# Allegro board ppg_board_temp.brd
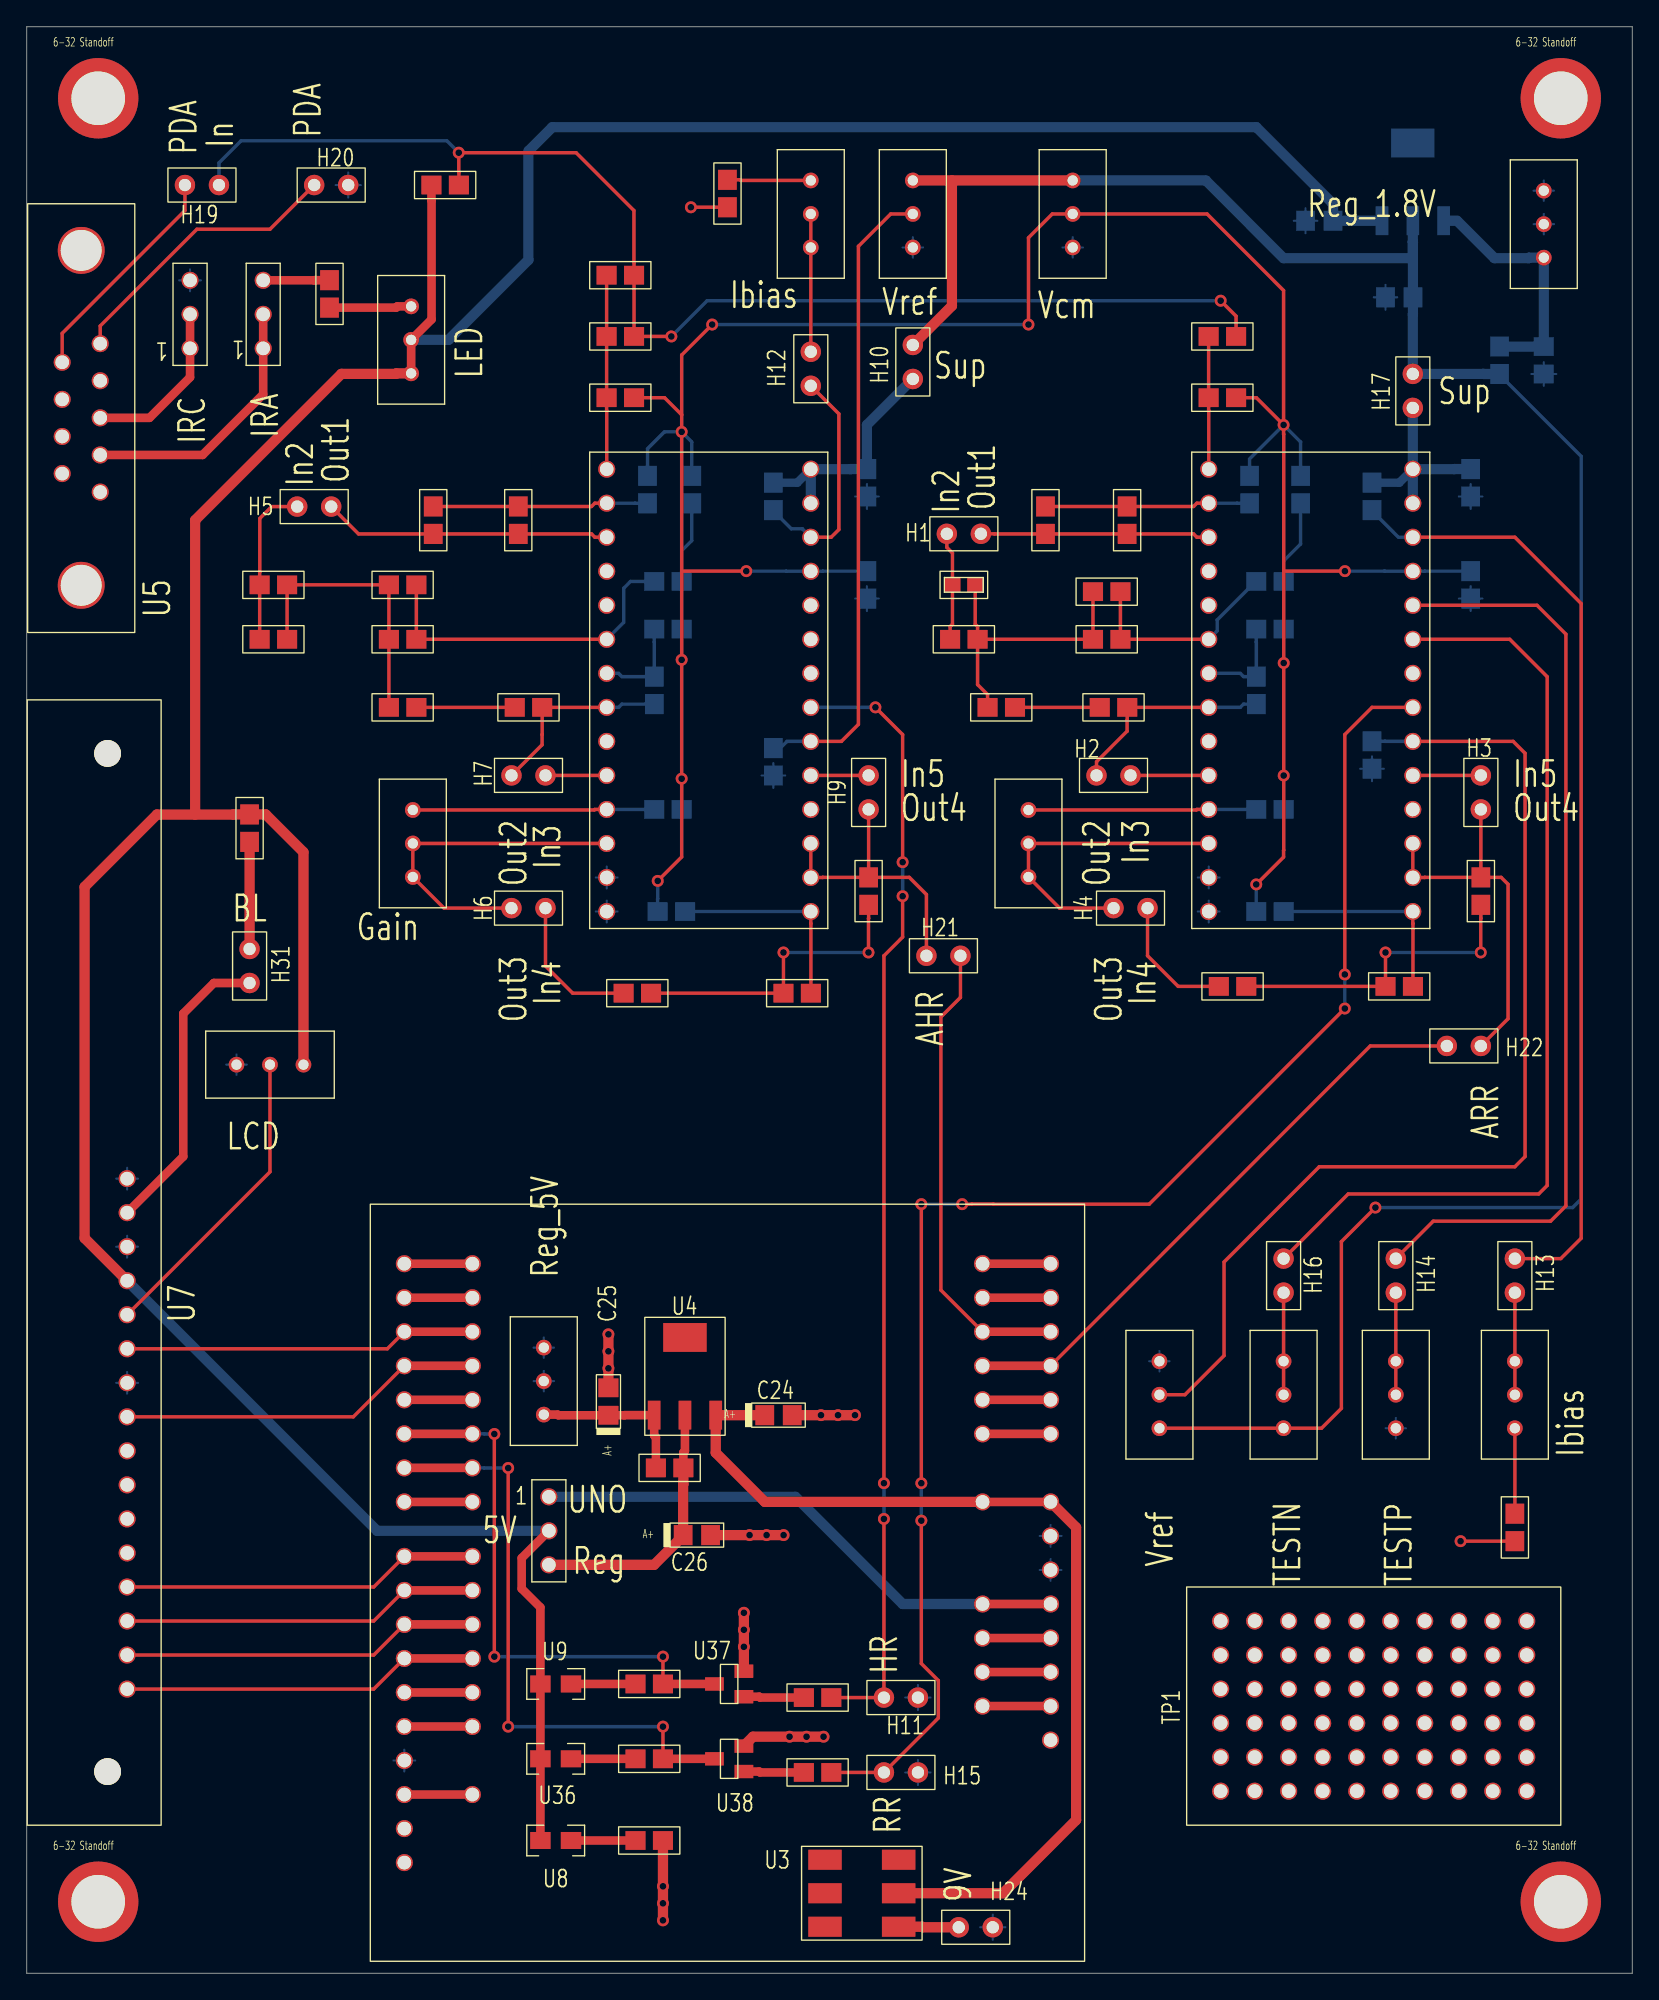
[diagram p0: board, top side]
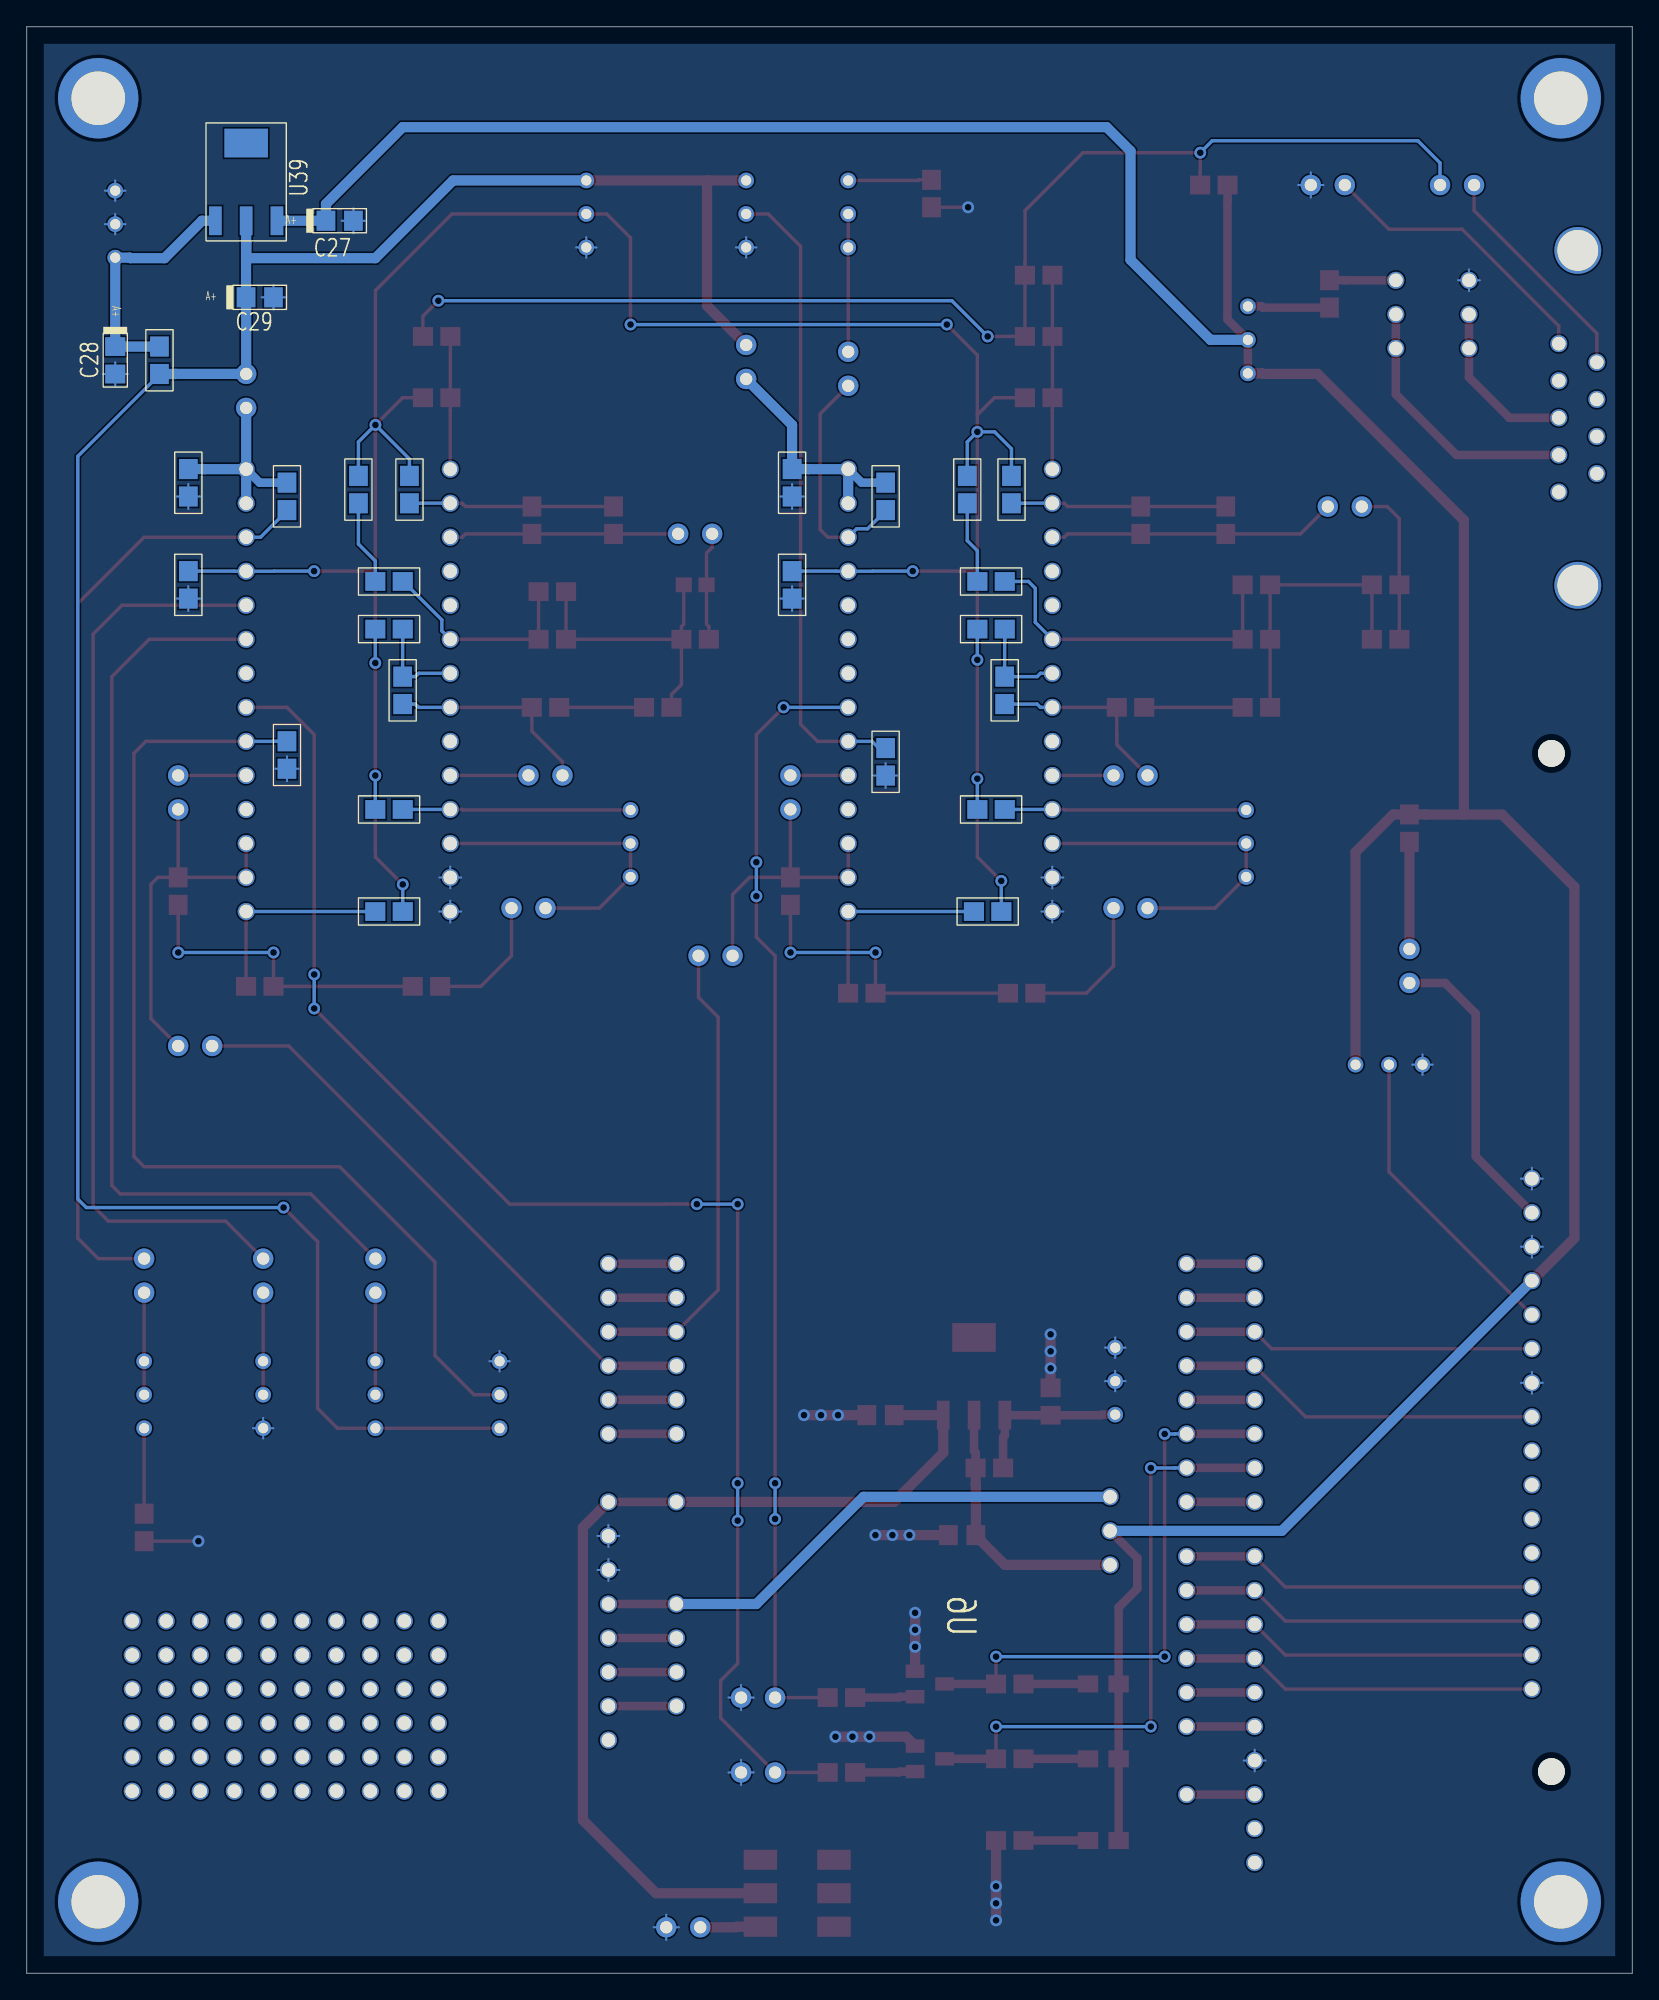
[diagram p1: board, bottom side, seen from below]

Outline 119.89 x 145.29 mm; copper layers: TOP, BOTTOM. Coordinates in mm from the lower left corner of the outline.
Outline path: 0,145.29 0,0 119.89,0 119.89,145.29 0,145.29

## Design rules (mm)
net group A: nets A<0> A<1> A<2> A<3> A<4> A<5>
net group PB: nets PB<0> PB<1> PB<2> PB<3> PB<4> PB<5>
net group PD: nets PD<0> PD<1> PD<2> PD<3> PD<4> PD<5> PD<6> PD<7>

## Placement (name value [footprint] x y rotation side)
C1  -  [GR_0805]  89.28 122.17 180 top
C2  -  [GR_0805]  82.17 108.46 270 top
C3  -  [GR_0603]  69.98 103.63 0 top
C4  -  [GR_0805]  69.98 99.57 0 top
C5  -  [GR_0805]  80.65 99.57 0 top
C6  -  [GR_0805]  80.65 103.12 0 top
C7  -  [GR_0805]  44.32 126.75 0 top
C8  -  [GR_0805]  44.32 122.17 0 top
C9  -  [GR_0805]  36.7 108.46 90 top
C10  -  [GR_0805]  18.41 103.63 180 top
C11  -  [GR_0805]  18.41 99.57 180 top
C12  -  [GR_0805]  28.07 99.57 180 top
C13  -  [GR_0805]  28.07 103.63 180 top
C14  -  [GR_0805]  48.13 79.25 0 bottom
C15  -  [GR_0805]  55.75 90.42 90 bottom
C16  -  [GR_0805]  62.74 103.63 90 bottom
C17  -  [GR_0805]  55.75 110.24 270 bottom
C18  -  [GR_0805]  100.46 110.24 270 bottom
C19  -  [GR_0805]  107.82 103.63 90 bottom
C20  -  [GR_0805]  62.87 80.77 90 top
C21  -  [GR_0805]  92.84 79.25 0 bottom
C22  -  [GR_0805]  108.59 80.77 270 top
C23  -  [GR_0805]  100.46 90.93 90 bottom
C24  -  [GR_0805_TANT]  56.13 41.66 0 top
C25  -  [GR_0805_TANT]  43.43 42.67 90 top
C26  -  [GR_0805_TANT]  50.04 32.7 0 top
C27  -  [GR_0805_TANT]  96.52 130.81 180 bottom
C28  -  [GR_0805_TANT]  113.28 120.4 270 bottom
C29  -  [GR_0805_TANT]  102.49 125.09 180 bottom
C30  -  [GR_0805]  62.74 111.25 90 bottom
C31  -  [GR_0805]  107.82 111.25 90 bottom
H1  -  [JUMPER2]  71.25 107.44 180 top
H2  -  [JUMPER2]  79.88 89.41 0 top
H3  -  [JUMPER2]  108.59 89.41 270 top
H4  -  [JUMPER2]  81.15 79.5 0 top
H5  -  [JUMPER2]  20.19 109.47 0 top
H6  -  [JUMPER2]  38.73 79.5 180 top
H7  -  [JUMPER2]  38.73 89.41 180 top
H8  -  [GR_HEADER_SIP3]  12.19 123.83 180 top
H9  -  [JUMPER2]  62.87 86.87 90 top
H10  -  [JUMPER2]  66.17 119 90 top
H11  -  [JUMPER2]  64.01 20.57 0 top
H12  -  [JUMPER2]  58.55 118.49 90 top
H13  -  [JUMPER2]  111.12 53.34 270 top
H14  -  [JUMPER2]  102.23 53.34 270 top
H15  -  [JUMPER2]  64.01 14.99 0 top
H16  -  [JUMPER2]  93.85 53.34 270 top
H17  -  [JUMPER2]  103.5 119.38 270 top
H18  -  [GR_HEADER_SIP3]  17.65 123.83 180 top
H19  -  [JUMPER2]  14.35 133.48 180 top
H20  -  [JUMPER2]  21.46 133.48 0 top
H21  -  [JUMPER2]  67.18 75.95 0 top
H22  -  [JUMPER2]  106.05 69.22 0 top
H23  -  [GR_HEADER_SIP3]  38.99 33.02 0 top
H24  -  [JUMPER2]  69.6 3.43 0 top
H31  -  [JUMPER2]  16.64 73.91 90 top
NOREF  -  [unnamed]  114.55 139.95 0 top
NOREF#2  -  [unnamed]  5.33 5.33 0 top
NOREF#3  -  [unnamed]  114.55 5.33 0 top
NOREF#4  -  [unnamed]  5.33 139.95 0 top
R1  -  [MURATAPV36W]  78.11 131.32 0 top
R2  -  [GR_0805]  46.86 95.76 90 bottom
R3  -  [GR_0805]  37.47 94.49 180 top
R4  -  [GR_0805]  47.88 100.33 0 bottom
R5  -  [MURATAPV36W]  111.12 43.18 0 top
R6  -  [MURATAPV36W]  66.17 131.32 0 top
R7  -  [MURATAPV36W]  102.23 43.18 0 top
R8  -  [MURATAPV36W]  58.55 131.32 180 top
R9  -  [GR_0805]  49.66 110.74 90 bottom
R10  -  [GR_0805]  47.88 103.89 0 bottom
R11  -  [GR_0805]  28.07 94.49 180 top
R12  -  [MURATAPV36W]  93.85 43.18 0 top
R13  -  [GR_0805]  30.35 108.46 90 top
R14  -  [GR_0805]  31.24 133.48 180 top
R15  -  [GR_0805]  46.36 110.74 90 bottom
R16  -  [GR_0805]  44.32 117.6 0 top
R17  -  [MURATAPV36W]  84.58 43.18 180 top
R18  -  [GR_0805]  45.59 73.15 0 top
R19  -  [MURATAPV36W]  74.8 84.33 0 top
R20  -  [GR_0805]  57.53 73.15 0 top
R21  -  [MURATAPV36W]  28.83 84.33 180 top
R22  -  [GR_0805]  89.28 117.6 0 top
R23  -  [GR_0805]  91.31 110.74 90 bottom
R24  -  [GR_0805]  76.07 108.46 270 top
R25  -  [GR_0805]  72.77 94.49 0 top
R26  -  [GR_0805]  95.12 110.74 90 bottom
R27  -  [GR_0805]  92.84 103.89 0 bottom
R28  -  [GR_0805]  92.84 100.33 0 bottom
R29  -  [GR_0805]  81.15 94.49 0 top
R30  -  [GR_0805]  91.82 95.76 270 bottom
R31  -  [GR_0805]  47.88 86.87 0 bottom
R32  -  [GR_0805]  92.84 86.87 0 bottom
R33  -  [GR_0805]  102.49 73.66 180 top
R34  -  [GR_0805]  90.04 73.66 180 top
R35  -  [MURATAPV36W]  18.16 67.82 270 top
R36  -  [GR_0805]  16.64 85.47 270 top
R37  -  [GR_0805]  52.32 132.84 270 top
R38  -  [GR_0805]  111.12 33.27 90 top
R39  -  [MURATAPV36W]  28.7 121.92 0 top
R40  -  [GR_0805]  22.61 125.35 270 top
R41  -  [GR_0805]  48.01 37.72 0 top
R42  -  [MURATAPV36W]  38.61 44.2 180 top
R43  -  [GR_0805]  109.98 120.4 270 bottom
R44  -  [MURATAPV36W]  113.28 130.56 180 top
R45  -  [GR_0805]  46.48 9.91 180 top
R46  -  [GR_0805]  46.48 16 180 top
R47  -  [GR_0805]  59.05 20.57 180 top
R48  -  [GR_0805]  46.48 21.59 180 top
R49  -  [GR_0805]  59.05 14.99 180 top
TP1  -  [GR_TP_60]  89.15 13.59 90 top
U1  -  [DIP28_SOCKET]  50.93 95.76 0 top
U2  -  [DIP28_SOCKET]  95.89 95.76 0 top
U3  -  [GR_DPDT]  62.36 5.97 0 top
U4  -  [GR_SOT223-4]  49.15 41.66 90 top
U5  -  [GR_DB9_AE10924-ND]  4.06 116.08 270 top
U6  -  [GR_ARDUINO_UNO_REV3]  78.99 -10.54 90 top
U7  -  [GR_LCD_NHD-0216BZ-FL-YBW]  10.03 11.05 90 top
U8  -  [GR_0805_POLARIZED]  39.5 9.91 0 top
U9  -  [GR_0805_POLARIZED]  39.5 21.59 0 top
U10  -  [HEADER_SIP1]  71.37 22.48 270 bottom
U11  -  [HEADER_SIP1]  33.27 13.34 270 bottom
U12  -  [HEADER_SIP1]  71.37 52.96 270 bottom
U13  -  [HEADER_SIP1]  71.37 50.42 270 bottom
U14  -  [HEADER_SIP1]  71.37 47.88 270 bottom
U15  -  [HEADER_SIP1]  71.37 25.02 270 bottom
U16  -  [HEADER_SIP1]  71.37 35.18 270 bottom
U17  -  [HEADER_SIP1]  71.37 27.56 270 bottom
U18  -  [HEADER_SIP1]  71.37 45.34 270 bottom
U19  -  [HEADER_SIP1]  71.37 42.8 270 bottom
U20  -  [HEADER_SIP1]  71.37 40.26 270 bottom
U21  -  [HEADER_SIP1]  71.37 19.94 270 bottom
U22  -  [HEADER_SIP1]  33.27 35.18 270 bottom
U23  -  [HEADER_SIP1]  33.27 37.72 270 bottom
U24  -  [HEADER_SIP1]  33.27 40.26 270 bottom
U25  -  [HEADER_SIP1]  33.27 42.8 270 bottom
U26  -  [HEADER_SIP1]  33.27 18.42 270 bottom
U27  -  [HEADER_SIP1]  33.27 20.96 270 bottom
U28  -  [HEADER_SIP1]  33.27 23.5 270 bottom
U29  -  [HEADER_SIP1]  33.27 45.34 270 bottom
U30  -  [HEADER_SIP1]  33.27 47.88 270 bottom
U31  -  [HEADER_SIP1]  33.27 50.42 270 bottom
U32  -  [HEADER_SIP1]  33.27 52.96 270 bottom
U33  -  [HEADER_SIP1]  33.27 26.04 270 bottom
U34  -  [HEADER_SIP1]  33.27 28.58 270 bottom
U35  -  [HEADER_SIP1]  33.27 31.12 270 bottom
U36  -  [GR_0805_POLARIZED]  39.5 16 0 top
U37  -  [GR_SOT23]  52.45 21.59 90 top
U38  -  [GR_SOT23]  52.45 16 90 top
U39  -  [GR_SOT223-4]  103.5 130.81 90 bottom

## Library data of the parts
C1 = GR_CAP: part number: GR_CAP-1.2UF,GR_0805,10%
C2 C13 = GR_CAP: part number: GR_CAP-150NF,GR_0805,10%
C3 = GR_CAP: part number: GR_CAP-15UF,GR_0603,20%
C4 = GR_CAP: part number: GR_CAP-1UF,GR_0805,10%
C5 = GR_CAP: part number: GR_CAP-4.7UF,GR_0805,10%
C6 C10 = GR_CAP: part number: GR_CAP-1.5UF,GR_0805,10%
C7 = GR_CAP: part number: GR_CAP-120NF,GR_0805,5%
C8 C12 = GR_CAP: part number: GR_CAP-470NF,GR_0805,10%
C9 C11 C14 C20-C22 = GR_CAP: part number: GR_CAP-100NF,GR_0805,10%
C15-C19 C23 C30 C31 = GR_CAP: part number: GR_CAP-10NF,GR_0805,10%
C24-C29 = GR_CAP_TANT: part number: GR_CAP_TANT-1UF,GR_0805_TANT
H1-H7 H9-H17 H19-H22 H24 H31 = HEADER_SIP2: part number: HEADER_SIP2-SIP HEADER
H8 H18 H23 = GR_HEADER_SIP3
R1 R42 R44 = POT: part number: POT-1K,MURATAPV36W
R2 R30 = GR_RES: part number: GR_RES-40.2K,1%,GR_0805
R3 R10 = GR_RES: part number: GR_RES-619K,1%,GR_0805
R4 R28 R32 R37 R38 R47 R49 = GR_RES: part number: GR_RES-10K,1%,GR_0805
R5 R7 R8 R12 = POT: part number: POT-500K,MURATAPV36W
R6 R17 = POT: part number: POT-200K,MURATAPV36W
R9 R26 = GR_RES: part number: GR_RES-0,JUMPER,GR_0805
R11 = GR_RES: part number: GR_RES-976K,1%,GR_0805
R13 R16 = GR_RES: part number: GR_RES-499K,1%,GR_0805
R14 R15 = GR_RES: part number: GR_RES-100K,1%,GR_0805
R18 R20 = GR_RES: part number: GR_RES-110K,1%,GR_0805
R19 R21 = POT: part number: POT-100K,MURATAPV36W
R22 = GR_RES: part number: GR_RES-3.01M,1%,GR_0805
R23 R33 R34 = GR_RES: part number: GR_RES-1.00M,1%,GR_0805
R24 = GR_RES: part number: GR_RES-4.99M,1%,GR_0805
R25 = GR_RES: part number: GR_RES-9.76M,1%,GR_0805
R27 R29 = GR_RES: part number: GR_RES-6.19M,1%,GR_0805
R31 = GR_RES: part number: GR_RES-49.9K,1%,GR_0805
R35 = POT: part number: POT-10K,MURATAPV36W
R36 = GR_RES: part number: GR_RES-220,1%,GR_0805
R39 = POT: part number: POT-200,MURATAPV36W
R40 = GR_RES: part number: GR_RES-100,1%,GR_0805
R41 R43 R45 R46 R48 = GR_RES: part number: GR_RES-240,1%,GR_0805
TP1 = TP60
U1 U2 = DIP28_SOCKET
U3 = GR_SWITCH_DPDT
U4 U39 = GR_LM317A
U5 = GR_NELLCOR_DB9
U6 = GR_ARDUINO_UNO_REV3
U7 = GR_LCD
U8 U9 U36 = GR_LED: part number: GR_LED-660NM,GR_0805_POLARIZED,20MA
U10-U35 = GR_HEADER_SIP1
U37 U38 = GR_MBT2222

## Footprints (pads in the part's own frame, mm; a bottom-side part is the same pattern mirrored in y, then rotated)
DIP28_SOCKET
  round 1.27 hole 1.016: 1(-7.62,16.51) 2(-7.62,13.97) 3(-7.62,11.43) 4(-7.62,8.89) 5(-7.62,6.35) 6(-7.62,3.81) 7(-7.62,1.27) 8(-7.62,-1.27) 9(-7.62,-3.81) 10(-7.62,-6.35) 11(-7.62,-8.89) 12(-7.62,-11.43) 13(-7.62,-13.97) 14(-7.62,-16.51) 15(7.62,-16.51) 16(7.62,-13.97) 17(7.62,-11.43) 18(7.62,-8.89) 19(7.62,-6.35) 20(7.62,-3.81) 21(7.62,-1.27) 22(7.62,1.27) 23(7.62,3.81) 24(7.62,6.35) 25(7.62,8.89) 26(7.62,11.43) 27(7.62,13.97) 28(7.62,16.51)
GR_0603
  rect 1.2x1.1 smd: 1(-0.85,0) 2(0.85,0)
GR_0805
  rect 1.5x1.4 smd: 1(-1.025,0) 2(1.025,0)
GR_0805_POLARIZED
  rect 1.524x1.27 smd: 1(-1.143,0) 2(1.143,0)
GR_0805_TANT
  rect 1.4x1.5 smd: 1(-1.025,0) 2(1.025,0)
GR_ARDUINO_UNO_REV3
  round 1.27 hole 1.016: 1(27.94,2.54) 2(30.48,2.54) 3(33.02,2.54) 4(35.56,2.54) 5(38.1,2.54) 6(40.64,2.54) 7(43.18,2.54) 8(45.72,2.54) 9(50.8,2.54) 10(53.34,2.54) 11(55.88,2.54) 12(58.42,2.54) 13(60.96,2.54) 14(63.5,2.54) 15(63.5,50.8) 16(60.96,50.8) 17(58.42,50.8) 18(55.88,50.8) 19(53.34,50.8) 20(50.8,50.8) 21(48.26,50.8) 22(45.72,50.8) 23(41.656,50.8) 24(39.116,50.8) 25(36.576,50.8) 26(34.036,50.8) 27(31.496,50.8) 28(28.956,50.8) 29(26.416,50.8) 30(23.876,50.8) 31(21.336,50.8) 32(18.796,50.8)
GR_DB9_AE10924-ND
  round 3.5 hole 3.05: (-12.52,0) (12.48,0)
  round 1.27 hole 1.016: 1(5.52,1.42) 2(2.75,1.42) 3(-0.02,1.42) 4(-2.79,1.42) 5(-5.56,1.42) 6(4.14,-1.42) 7(1.37,-1.42) 8(-1.4,-1.42) 9(-4.17,-1.42)
GR_DPDT
  rect 2.5x1.5 smd: 1(-2.75,2.5) 2(-2.75,0) 3(-2.75,-2.5) 4(2.75,-2.5) 5(2.75,0) 6(2.75,2.5)
GR_HEADER_SIP3
  round 1.27 hole 1.016: 1(0,2.54) 2(0,0) 3(0,-2.54)
GR_LCD_NHD-0216BZ-FL-YBW
  round 2 hole 2.5 unplated: (4,4) (80,4)
  round 1.27 hole 1.016: 1(43.18,2.54) 2(40.64,2.54) 3(38.1,2.54) 4(35.56,2.54) 5(33.02,2.54) 6(30.48,2.54) 7(27.94,2.54) 8(25.4,2.54) 9(22.86,2.54) 10(20.32,2.54) 11(17.78,2.54) 12(15.24,2.54) 13(12.7,2.54) 14(10.16,2.54) 15(45.72,2.54) 16(48.26,2.54)
GR_SOT23
  rect 1x1.4 smd: 1(-0.95,-1.1) 2(0.95,-1.1) 3(0,1.1)
GR_SOT223-4
  rect 2.15x0.95 smd: 1(0,2.3) 2(0,0) 3(0,-2.3)
  rect 2.15x3.25 smd: 4(5.8,0)
GR_TP_60
  round 1.27 hole 1.016: 1(0,0) 2(2.54,0) 3(5.08,0) 4(7.62,0) 5(10.16,0) 6(12.7,0) 7(0,-2.54) 8(2.54,-2.54) 9(5.08,-2.54) 10(7.62,-2.54) 11(10.16,-2.54) 12(12.7,-2.54) 13(0,-5.08) 14(2.54,-5.08) 15(5.08,-5.08) 16(7.62,-5.08) 17(10.16,-5.08) 18(12.7,-5.08) 19(0,-7.62) 20(2.54,-7.62) 21(5.08,-7.62) 22(7.62,-7.62) 23(10.16,-7.62) 24(12.7,-7.62) 25(0,-10.16) 26(2.54,-10.16) 27(5.08,-10.16) 28(7.62,-10.16) 29(10.16,-10.16) 30(12.7,-10.16) 31(0,-12.7) 32(2.54,-12.7) 33(5.08,-12.7) 34(7.62,-12.7) 35(10.16,-12.7) 36(12.7,-12.7) 37(0,-15.24) 38(2.54,-15.24) 39(5.08,-15.24) 40(7.62,-15.24) 41(10.16,-15.24) 42(12.7,-15.24) 43(0,-17.78) 44(2.54,-17.78) 45(5.08,-17.78) 46(7.62,-17.78) 47(10.16,-17.78) 48(12.7,-17.78) 49(0,-20.32) 50(2.54,-20.32) 51(5.08,-20.32) 52(7.62,-20.32) 53(10.16,-20.32) 54(12.7,-20.32) 55(0,-22.86) 56(2.54,-22.86) 57(5.08,-22.86) 58(7.62,-22.86) 59(10.16,-22.86) 60(12.7,-22.86)
HEADER_SIP1
  round 1.27 hole 1.016: 1(0,0)
JUMPER2
  round 1.524 hole 0.914: 1(0,0) 2(2.54,0)
MURATAPV36W
  round 1.168 hole 0.762: 1(0,2.5) 2(0,0) 3(0,-2.5)
unnamed
  round 6 hole 4 unplated: (0,0)

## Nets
GND: C15.1 C16.1 C19.1 C23.1 C24.2(MINUS) C25.2(MINUS) C26.2(MINUS) C27.2(MINUS) C28.2(MINUS) C29.2(MINUS) C30.1 C31.1 H8.3 H11.2 H15.2 H20.2 H24.2 R1.3 R6.3 R7.3 R17.3 R35.3 R37.2 R38.1 R42.2 R42.3 R44.2 R44.3 R45.1 U1.13 U1.14 U2.13 U2.14 U6.6 U6.7 U6.29 U7.1 U7.5(RW) U7.16 U37.2(EMITTER) U38.2(EMITTER)
VBAT_9V: C24.1(PLUS) U3.5 U4.3(VIN) U6.8(VIN_UNREG) U16.1(IN)
VDD_3V3: U6.4(VDD_3V3) U15.1(IN)
VDD_5: C27.1(PLUS) H23.2 R14.2 R35.1 R36.1 R39.2 R39.3 U7.2(VDD_5) U8.1(ANODE) U9.1(ANODE) U36.1(ANODE) U39.3(VIN)
VDD_5V_REG: C26.1(PLUS) H23.3 R41.2 U4.2(VOUT)
VDD_5V_UNO: H23.1 U6.5(VDD_5V) U17.1(IN)
VDD_18: C29.1(PLUS) H10.2 H17.1 R1.1 R6.1 R12.3 R17.1 R43.2 U39.2(VOUT)
A<0>: U6.9(A<0>) U20.1(IN)
A<1>: U6.10(A<1>) U19.1(IN)
A<2>: H22.1 U6.11(A<2>) U18.1(IN)
A<3>: H21.2 U6.12(A<3>) U14.1(IN)
A<4>: U6.13(A<4>) U13.1(IN)
A<5>: U6.14(A<5>) U12.1(IN)
AREF_UNO: U6.30(AREF) U11.1(IN)
IOREF_UNO: U6.2(IOREF) U21.1(IN)
OUT_HR: H11.1 R47.1 U1.21(VOUT_COMP)
OUT_RR: H15.1 R49.1 U2.21(VOUT_COMP)
PB<0>: U6.23(PB<0>) U7.11(DB4) U35.1(IN)
PB<1>: U6.24(PB<1>) U7.12(DB5) U34.1(IN)
PB<2>: U6.25(PB<2>) U7.13(DB6) U33.1(IN)
PB<3>: U6.26(PB<3>) U7.14(DB7) U28.1(IN)
PB<4>: U6.27(PB<4>) U27.1(IN)
PB<5>: U6.28(PB<5>) U26.1(IN)
PD<0>: U6.15(PD<0>) U32.1(IN)
PD<1>: U6.16(PD<1>) U31.1(IN)
PD<2>: U6.17(PD<2>) U7.4(RS) U30.1(IN)
PD<3>: U6.18(PD<3>) U7.6(E) U29.1(IN)
PD<4>: U6.19(PD<4>) U25.1(IN)
PD<5>: R48.1 U6.20(PD<5>) U24.1(IN) U37.3(COLLECTOR)
PD<6>: R46.1 U6.21(PD<6>) U23.1(IN) U38.3(COLLECTOR)
PD<7>: U6.22(PD<7>) U22.1(IN)
RESET_UNO: U6.3(RESET) U10.1(IN)
UNNAMED_1_DIP28SOCKET_I171_IBIA: C18.2 H13.1 U2.26(IBIAS)
UNNAMED_1_DIP28SOCKET_I171_OUT2: H2.1 R29.2 R30.2 U2.8(OUT2)
UNNAMED_1_DIP28SOCKET_I171_TE_1: H14.1 U2.24(TESTP)
UNNAMED_1_DIP28SOCKET_I171_TEST: H16.1 U2.23(TESTN)
UNNAMED_1_DIP28SOCKET_I171_VDDA: C18.1 C31.2 H17.2 U2.27(VDDA1) U2.28(VDDA2)
UNNAMED_1_DIP28SOCKET_I171_VI_1: C2.1 R23.1 R24.1 U2.2(VIN1-)
UNNAMED_1_DIP28SOCKET_I171_VI_2: R28.1 R30.1 U2.7(VIN2-)
UNNAMED_1_DIP28SOCKET_I171_VI_3: R19.1 R32.1 U2.11(VIN3-)
UNNAMED_1_DIP28SOCKET_I171_VI_4: C22.1 H3.2 H22.2 U2.16(VIN4-) U2.17(VOUT4)
UNNAMED_1_DIP28SOCKET_I171_VIN1: C1.2 R22.1 U2.1(VIN1+)
UNNAMED_1_DIP28SOCKET_I171_VIN2: C5.2 C6.2 R27.1 U2.6(VIN2+)
UNNAMED_1_DIP28SOCKET_I171_VIN3: H2.2 U2.10(VIN3+)
UNNAMED_1_DIP28SOCKET_I171_VIN4: C21.2 R33.1 U2.15(VIN4+)
UNNAMED_1_DIP28SOCKET_I171_VINC: H3.1 U2.19(VIN_COMP)
UNNAMED_1_DIP28SOCKET_I171_VOUT: C2.2 H1.1 R24.2 U2.3(VOUT1)
UNNAMED_1_DIP28SOCKET_I171_VREF: C23.2 R17.2 U2.20(VREF_COMP)
UNNAMED_1_DIP28SOCKET_I172_IBIA: C17.2 H12.1 U1.26(IBIAS)
UNNAMED_1_DIP28SOCKET_I172_OUT2: H7.2 R2.1 R3.1 U1.8(OUT2)
UNNAMED_1_DIP28SOCKET_I172_VDDA: C17.1 C30.2 H10.1 U1.27(VDDA1) U1.28(VDDA2)
UNNAMED_1_DIP28SOCKET_I172_VI_1: C7.1 C8.1 R16.1 U1.1(VIN1+)
UNNAMED_1_DIP28SOCKET_I172_VI_2: C12.1 C13.1 R10.1 U1.6(VIN2+)
UNNAMED_1_DIP28SOCKET_I172_VI_3: H7.1 U1.10(VIN3+)
UNNAMED_1_DIP28SOCKET_I172_VI_4: C20.2 H9.1 H21.1 U1.16(VIN4-) U1.17(VOUT4)
UNNAMED_1_DIP28SOCKET_I172_VIN1: C9.2 R13.2 R15.1 U1.2(VIN1-)
UNNAMED_1_DIP28SOCKET_I172_VIN2: R2.2 R4.1 U1.7(VIN2-)
UNNAMED_1_DIP28SOCKET_I172_VIN3: R21.3 R31.1 U1.11(VIN3-)
UNNAMED_1_DIP28SOCKET_I172_VIN4: C14.2 R20.2 U1.15(VIN4+)
UNNAMED_1_DIP28SOCKET_I172_VINC: H9.2 U1.19(VIN_COMP)
UNNAMED_1_DIP28SOCKET_I172_VOUT: C9.1 H5.2 R13.1 U1.3(VOUT1)
UNNAMED_1_DIP28SOCKET_I172_VREF: C15.2 R6.2 U1.20(VREF_COMP)
UNNAMED_1_GRCAP_IC3RR_1: C3.1 C4.1 H1.2
UNNAMED_1_GRCAP_IC3RR_2: C3.2 C4.2 C5.1 C6.1 R25.1
UNNAMED_1_GRCAP_IC4HR_1: C10.1 C11.1 C12.2 C13.2 R11.2
UNNAMED_1_GRCAP_IC4HR_2: C10.2 C11.2 H5.1
UNNAMED_1_GRCAP_IC7RR_2: C22.2 R33.2 R34.1
UNNAMED_1_GRCAP_IC9HR_1: C20.1 R18.2 R20.1
UNNAMED_1_GRHEADERSIP3_I131_1: H8.1 H8.2 U5.3(IR_CATHODE)
UNNAMED_1_GRHEADERSIP3_I132_1: H18.1 H18.2 U5.2(IR_ANODE)
UNNAMED_1_GRHEADERSIP3_I132_3: H18.3 R40.1
UNNAMED_1_GRLCD_I79_V0: R35.2 U7.3(V0)
UNNAMED_1_GRLCD_I79_VDDBL: H31.1 U7.15(VDD_BL)
UNNAMED_1_GRLED_I155_CATHODE: R45.2 U8.2(CATHODE)
UNNAMED_1_GRLED_I169_CATHODE: R46.2 U36.2(CATHODE)
UNNAMED_1_GRLED_I170_CATHODE: R48.2 U9.2(CATHODE)
UNNAMED_1_GRLM317A_I135_ADJ: C25.1(PLUS) R41.1 R42.1 U4.1(ADJ)
UNNAMED_1_GRLM317A_I139_ADJ: C28.1(PLUS) R43.1 R44.1 U39.1(ADJ)
UNNAMED_1_GRMBT2222_I163_BASE: R49.2 U38.1(BASE)
UNNAMED_1_GRMBT2222_I165_BASE: R47.2 U37.1(BASE)
UNNAMED_1_GRNELLCORDB9_I71_PDAN: H20.1 U5.5(PD_ANODE)
UNNAMED_1_GRNELLCORDB9_I71_PDCA: H19.2 U5.9(PD_CATHODE)
UNNAMED_1_GRRES_I96_2: H31.2 R36.2
UNNAMED_1_GRRES_I133_2: R39.1 R40.2
UNNAMED_1_GRRES_IR4HR_2: R9.1 R10.2
UNNAMED_1_GRRES_IR4RR_2: R26.1 R27.2
UNNAMED_1_GRRES_IR6RR_2: R25.2 R29.1
UNNAMED_1_GRRES_IR7HR_2: R3.2 R11.1
UNNAMED_1_GRRES_IR12HR_1: H6.1 R18.1
UNNAMED_1_GRRES_IRPBIASHR_1: R8.3 R37.1
UNNAMED_1_GRRES_IRPBIASRR_2: R5.3 R38.2
UNNAMED_1_HEADERSIP2_I40_1: H4.1 R19.2 R19.3 U2.12(OUT3)
UNNAMED_1_HEADERSIP2_I40_2: H4.2 R34.2
UNNAMED_1_HEADERSIP2_I56_2: H6.2 R21.1 R21.2 U1.12(OUT3)
UNNAMED_1_HEADERSIP2_I66_2: H12.2 R8.1 R8.2
UNNAMED_1_POT_I4_2: H13.2 R5.1 R5.2
UNNAMED_1_POT_I45_1: H16.2 R12.1 R12.2
UNNAMED_1_POT_I46_1: H14.2 R7.1 R7.2
VCM: C14.1 C16.2 C19.2 C21.1 R1.2 R4.2 R9.2 R15.2 R16.2 R22.2 R23.2 R26.2 R28.2 R31.2 R32.2 U1.25(VCMA) U2.25(VCMA)
VOUT_PD: C1.1 C7.2 C8.2 H19.1 R14.1
VSUP: H24.1 U3.4

Pads without a net: TP1 1 2 3 4 5 6 7 8 9 10 11 12 13 14 15 16 17 18 19 20 21 22 23 24 25 26 27 28 29 30 31 32 33 34 35 36 37 38 39 40 41 42 43 44 45 46 47 48 49 50 51 52 53 54 55 56 57 58 59 60; U1 4 5 9 18 22 23 24; U2 4 5 9 18 22; U3 1 2 3 6; U4 4; U5 1 4 6 7 8; U6 1 31 32; U7 7 8 9 10; U39 4

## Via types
v1: diameter 0.889, hole 0.508, TOP to BOTTOM, 57 vias

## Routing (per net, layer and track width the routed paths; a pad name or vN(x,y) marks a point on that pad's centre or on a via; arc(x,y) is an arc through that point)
GND: length 148.3
  TOP w0.254: R37.2 v1(49.59,131.82) ; R38.1 v1(107.07,32.25)
  TOP w0.762: C24.2 v1(59.31,41.66) v1(60.58,41.66) v1(61.85,41.66) ; v1(43.43,47.69) v1(43.43,46.42) v1(43.43,45.15) C25.2 ; C26.2 v1(53.98,32.7) v1(55.25,32.7) v1(56.52,32.7) ; v1(53.55,26.9) v1(53.55,25.63) v1(53.55,24.36) U37.2 ; v1(59.5,17.65) v1(58.23,17.65) v1(56.96,17.65) 54.23,17.65 53.55,16.98 U38.2 ; v1(47.51,3.95) v1(47.51,5.22) v1(47.51,6.49) R45.1
  BOTTOM w0.152: 27.38,15.88 28.19,15.88 ; 28.19,15.88 28.19,16.69 ; 28.19,15.88 28.19,15.06 ; 28.19,15.88 29.01,15.88 ; 94.62,130.81 C27.2 ; C27.2 95.5,131.74 ; C27.2 96.37,130.81 ; C27.2 95.5,129.88 ; U6.7 77.27,32.64 ; U6.7 75.64,32.64 ; U6.7 76.45,33.45 ; U6.7 76.45,31.83 ; 7.49,53.42 U7.1 ; U7.1 8.31,54.23 ; U7.1 7.49,55.04 ; U7.1 6.68,54.23 ; 112.52,133.06 R44.3 ; R44.3 113.28,133.82 ; R44.3 113.28,132.29 ; R44.3 114.05,133.06 ; 72.14,2.49 H24.2 ; H24.2 71.2,3.43 ; H24.2 73.08,3.43 ; H24.2 72.14,4.37 ; 7.49,43.26 7.49,44.07 ; 7.49,44.07 7.49,44.88 ; 7.49,44.07 8.31,44.07 ; 7.49,44.07 6.68,44.07 ; C19.1 108.7,102.61 ; C19.1 107.82,101.68 ; C19.1 106.94,102.61 ; C19.1 107.82,103.54 ; 99.58,89.91 C23.1 ; C23.1 100.46,88.98 ; C23.1 100.46,90.84 ; C23.1 101.34,89.91 ; 15.66,67.06 R35.3 ; R35.3 15.66,68.58 ; R35.3 14.9,67.82 ; R35.3 16.42,67.82 ; 77.34,128.82 R1.3 ; R1.3 78.11,128.06 ; R1.3 78.11,129.58 ; R1.3 78.87,128.82 ; 66.17,128.06 R6.3 ; R6.3 66.93,128.82 ; R6.3 65.4,128.82 ; R6.3 66.17,129.58 ; 88.27,80.97 U2.13 ; U2.13 89.08,81.79 ; U2.13 88.27,82.6 ; U2.13 87.45,81.79 ; H15.2 66.55,15.93 ; H15.2 65.61,14.99 ; H15.2 66.55,14.05 ; H15.2 67.49,14.99 ; 84.58,44.92 R17.3 ; R17.3 85.34,45.68 ; R17.3 84.58,46.44 ; R17.3 83.82,45.68 ; R7.3 103,40.68 ; R7.3 102.23,39.92 ; R7.3 102.23,41.44 ; R7.3 101.47,40.68 ; 43.31,78.43 U1.14 ; U1.14 44.12,79.25 ; U1.14 42.49,79.25 ; U1.14 43.31,80.06 ; C28.2 114.21,119.37 ; C28.2 113.28,120.25 ; C28.2 112.36,119.37 ; C28.2 113.28,118.49 ; C31.1 107.82,111.16 ; C31.1 108.7,110.23 ; C31.1 107.82,109.3 ; C31.1 106.94,110.23 ; H8.3 12.19,127.18 ; H8.3 11.38,126.37 ; H8.3 12.19,125.55 ; H8.3 13.01,126.37 ; 61.86,110.23 C30.1 ; C30.1 62.74,111.16 ; C30.1 63.62,110.23 ; C30.1 62.74,109.3 ; R44.2 114.05,130.56 ; R44.2 113.28,129.79 ; R44.2 113.28,131.32 ; R44.2 112.52,130.56 ; R42.2 38.61,44.96 ; R42.2 39.37,44.2 ; R42.2 38.61,43.43 ; R42.2 37.85,44.2 ; 88.27,78.43 U2.14 ; U2.14 88.27,80.06 ; U2.14 89.08,79.25 ; U2.14 87.45,79.25 ; 6.68,59.31 U7.16 ; U7.16 8.31,59.31 ; U7.16 7.49,60.12 ; U7.16 7.49,58.5 ; R42.3 38.61,47.46 ; R42.3 39.37,46.7 ; R42.3 38.61,45.93 ; R42.3 37.85,46.7 ; C29.2 101.46,126.02 ; C29.2 101.46,124.17 ; C29.2 100.59,125.09 ; C29.2 102.34,125.09 ; 65.61,20.57 H11.2 ; H11.2 67.49,20.57 ; H11.2 66.55,21.51 ; H11.2 66.55,19.63 ; C16.1 63.62,102.61 ; C16.1 61.86,102.61 ; C16.1 62.74,103.54 ; C16.1 62.74,101.68 ; H20.2 24.94,133.48 ; H20.2 23.06,133.48 ; H20.2 24,134.42 ; H20.2 24,132.54 ; 42.49,81.79 U1.13 ; U1.13 43.31,82.6 ; U1.13 43.31,80.97 ; U1.13 44.12,81.79 ; 54.87,89.4 C15.1 ; C15.1 55.75,88.47 ; C15.1 56.63,89.4 ; C15.1 55.75,90.33 ; U6.6 77.27,30.1 ; U6.6 76.45,30.91 ; U6.6 76.45,29.29 ; U6.6 75.64,30.1
VBAT_9V: length 73
  TOP w0.635: U6.8 U16.1
  TOP w0.762: U3.5 72.9,5.97 78.36,11.43 78.36,33.27 U6.8 ; C24.1 U4.3 51.45,38.85 55.12,35.18 U16.1
VDD_3V3: length 5.1
  TOP w0.635: U6.4 U15.1
VDD_5: length 274.9
  TOP w0.635: U8.1 U36.1 U9.1 38.35,27.31 36.96,28.7 36.96,30.99 H23.2 ; R39.3 R39.2 30.23,123.44 30.23,132.32 30.22,132.33 R14.2
  TOP w0.762: 12.57,86.49 9.72,86.49 4.32,81.09 4.32,54.86 U7.2 ; 12.57,86.49 15.42,86.49 15.43,86.5 R36.1 17.85,86.5 20.66,83.68 R35.1 ; 12.57,86.49 12.57,108.46 23.5,119.38 27.57,119.38 27.61,119.42 R39.3
  BOTTOM w0.762: H23.2 26.16,33.02 U7.2 ; R39.2 31.5,121.92 37.47,127.89 37.47,136.02 39.24,137.8 91.82,137.8 97.54,132.07 C27.1 U39.3
VDD_5V_REG: length 20
  TOP w0.635: U4.2 49.15,38.98 49.03,38.86 R41.2
  TOP w0.762: R41.2 49.03,36.51 49.01,36.49 C26.1 49.01,32.65 46.84,30.48 H23.3
VDD_5V_UNO: length 40.8
  TOP w0.635: U6.5 U17.1
  BOTTOM w0.762: H23.1 57.4,35.56 65.41,27.56 U17.1
VDD_18: length 182.3
  TOP w0.254: v1(100.71,57.15) 98.17,54.61 98.17,42.16 96.69,40.68 R12.3 R17.1
  TOP w0.762: 69.09,133.82 69.09,124.46 66.17,121.54 ; 69.09,133.82 R1.1 ; 69.09,133.82 R6.1
  BOTTOM w0.254: v1(100.71,57.15) 115.44,57.15 116.08,57.79 116.08,113.23 109.98,119.32 R43.2
  BOTTOM w0.762: 103.5,129.23 103.51,129.22 C29.1 103.51,123.84 103.5,123.83 H17.1 108.77,119.38 108.77,119.37 R43.2 ; 103.5,129.23 U39.2 ; 103.5,129.23 103.5,129.22 103.5,128.02 93.85,128.02 88.05,133.82 R1.1
A<0>: length 5.1
  TOP w0.635: 76.45,40.26 U20.1
A<1>: length 5.1
  TOP w0.635: U6.10 U19.1
A<2>: length 44.6
  TOP w0.254: H22.1 100.33,69.22 U6.11
  TOP w0.635: U18.1 U6.11
A<3>: length 35
  TOP w0.254: U14.1 68.26,50.99 68.26,71.37 69.72,72.83 H21.2
  TOP w0.635: U6.12 U14.1
A<4>: length 5.1
  TOP w0.635: U6.13 U13.1
A<5>: length 5.1
  TOP w0.635: 76.45,52.96 U12.1
AREF_UNO: length 5.1
  TOP w0.635: U11.1 U6.30
IOREF_UNO: length 5.1
  TOP w0.635: U6.2 U21.1
OUT_HR: length 84.1
  TOP w0.254: v1(65.41,82.93) 65.41,92.46 v1(63.37,94.49) ; v1(64.01,36.58) 64.01,75.95 65.41,77.34 v1(65.41,80.39) ; v1(64.01,33.91) H11.1 R47.1
  BOTTOM w0.254: v1(63.37,94.49) U1.21 ; v1(64.01,33.91) v1(64.01,36.58) ; v1(65.41,80.39) v1(65.41,82.93)
OUT_RR: length 112.6
  TOP w0.254: v1(66.8,36.58) v1(66.8,57.4) ; v1(69.85,57.4) 70.57,57.4 70.58,57.42 72.17,57.42 72.18,57.4 83.82,57.4 v1(98.43,72.01) ; v1(98.43,74.55) 98.43,92.46 100.46,94.49 U2.21 ; R49.1 H15.1 68.07,19.05 68.07,21.84 66.8,23.11 v1(66.8,33.78)
  BOTTOM w0.254: v1(66.8,57.4) v1(69.85,57.4) ; v1(98.43,72.01) v1(98.43,74.55) ; v1(66.8,33.78) v1(66.8,36.58)
PB<0>: length 26.7
  TOP w0.254: U6.23 25.91,28.83 U7.11
  TOP w0.635: U35.1 U6.23
PB<1>: length 26.7
  TOP w0.254: U7.12 25.91,26.29 U6.24
  TOP w0.635: U34.1 U6.24
PB<2>: length 26.7
  TOP w0.254: U6.25 25.91,23.75 7.49,23.75
  TOP w0.635: U33.1 U6.25
PB<3>: length 26.7
  TOP w0.254: U6.26 25.91,21.21 U7.14
  TOP w0.635: U28.1 U6.26
PB<4>: length 5.1
  TOP w0.635: U27.1 28.19,20.96
PB<5>: length 5.1
  TOP w0.635: U26.1 U6.28
PD<0>: length 5.1
  TOP w0.635: U32.1 U6.15
PD<1>: length 5.1
  TOP w0.635: U31.1 U6.16
PD<2>: length 26.3
  TOP w0.254: U6.17 26.92,46.61 7.49,46.61
  TOP w0.635: U30.1 U6.17
PD<3>: length 27.4
  TOP w0.254: U7.6 24.38,41.53 U6.18
  TOP w0.635: U29.1 U6.18
PD<4>: length 5.1
  TOP w0.635: U25.1 U6.19
PD<5>: length 41.8
  TOP w0.254: v1(47.51,23.63) R48.1 ; v1(34.92,23.63) v1(34.92,40.25)
  TOP w0.635: U24.1 28.19,40.26 ; R48.1 U37.3
  BOTTOM w0.254: v1(47.51,23.63) v1(34.92,23.63) ; v1(34.92,40.25) 34.17,40.25 34.16,40.26 U24.1
PD<6>: length 44.9
  TOP w0.254: v1(35.95,18.41) v1(35.95,37.71) ; v1(47.51,18.41) R46.1
  TOP w0.635: R46.1 U38.3 ; U23.1 28.19,37.72
  BOTTOM w0.254: v1(47.51,18.41) v1(35.95,18.41) ; v1(35.95,37.71) 34.17,37.71 34.16,37.72 U23.1
PD<7>: length 5.1
  TOP w0.635: U22.1 U6.22
RESET_UNO: length 5.1
  TOP w0.635: U6.3 U10.1
UNNAMED_1_DIP28SOCKET_I171_IBIA: length 71.5
  TOP w0.254: U2.26 111.12,107.19 116.08,102.24 116.08,54.86 114.55,53.34 H13.1
  BOTTOM w0.254: U2.26 102.43,107.19 100.46,109.16 C18.2
UNNAMED_1_DIP28SOCKET_I171_OUT2: length 15.8
  TOP w0.254: H2.1 79.88,90.42 82.17,92.71 82.17,93.53 82.18,93.53 R29.2 U2.8
  BOTTOM w0.254: U2.8 90.62,94.49 90.87,94.73 R30.2
UNNAMED_1_DIP28SOCKET_I171_TE_1: length 69.3
  TOP w0.254: H14.1 105.03,56.13 113.79,56.13 114.94,57.28 114.94,99.95 112.78,102.11 U2.24
UNNAMED_1_DIP28SOCKET_I171_TEST: length 71.1
  TOP w0.254: U2.23 110.74,99.57 113.54,96.77 113.54,58.8 112.9,58.17 98.68,58.17 H16.1
UNNAMED_1_DIP28SOCKET_I171_VDDA: length 14.9
  BOTTOM w0.635: C18.1 102.5,111.26 U2.28
  BOTTOM w0.762: U2.28 106.61,112.27 106.61,112.28 C31.2 ; U2.28 U2.27 ; U2.28 H17.2
UNNAMED_1_DIP28SOCKET_I171_VI_1: length 15.3
  TOP w0.254: U2.2 87.38,109.73 87.13,109.48 C2.1 R24.1
  BOTTOM w0.254: U2.2 90.35,109.73 90.36,109.72 R23.1
UNNAMED_1_DIP28SOCKET_I171_VI_2: length 7.2
  BOTTOM w0.254: U2.7 90.62,97.03 90.87,96.78 R30.1 91.82,99.37 91.81,99.38 R28.1
UNNAMED_1_DIP28SOCKET_I171_VI_3: length 17
  TOP w0.254: U2.11 87.38,86.87 87.34,86.83 R19.1
  BOTTOM w0.254: R32.1 U2.11
UNNAMED_1_DIP28SOCKET_I171_VI_4: length 27.8
  TOP w0.254: C22.1 110.1,81.8 110.62,81.28 110.62,71.25 H22.2 ; C22.1 104.4,81.8 104.39,81.79 U2.16 U2.17 ; C22.1 H3.2
UNNAMED_1_DIP28SOCKET_I171_VIN1: length 9.9
  TOP w0.254: C1.2 R22.1 88.26,116.65 88.27,116.64 U2.1
UNNAMED_1_DIP28SOCKET_I171_VIN2: length 16
  TOP w0.254: C6.2 C5.2 U2.6
  BOTTOM w0.254: U2.6 88.89,100.2 88.89,101.02 91.76,103.89 R27.1
UNNAMED_1_DIP28SOCKET_I171_VIN3: length 5.8
  TOP w0.254: H2.2 U2.10
UNNAMED_1_DIP28SOCKET_I171_VIN4: length 15.2
  TOP w0.254: R33.1 103.51,78.35 103.5,78.36 U2.15
  BOTTOM w0.254: U2.15 C21.2
UNNAMED_1_DIP28SOCKET_I171_VINC: length 5.1
  TOP w0.254: U2.19 H3.1
UNNAMED_1_DIP28SOCKET_I171_VOUT: length 17.1
  TOP w0.254: U2.3 87.38,107.19 87.13,107.43 C2.2 R24.2 72.27,107.43 72.26,107.44 H1.1
UNNAMED_1_DIP28SOCKET_I171_VREF: length 80.7
  TOP w0.254: R17.2 86.49,43.18 89.41,46.1 89.41,53.09 96.52,60.2 111.12,60.2 111.89,60.96 111.89,91.06 111,91.95 U2.20
  BOTTOM w0.254: C23.2 101.41,91.96 101.42,91.95 U2.20
UNNAMED_1_DIP28SOCKET_I172_IBIA: length 17.6
  TOP w0.254: H12.1 60.64,116.4 60.64,107.76 60.07,107.19 U1.26
  BOTTOM w0.254: C17.2 55.75,109.16 57.1,107.82 57.92,107.82 U1.26
UNNAMED_1_DIP28SOCKET_I172_OUT2: length 14.5
  TOP w0.254: H7.2 38.48,91.69 38.48,92.46 38.49,92.46 R3.1 U1.8
  BOTTOM w0.254: R2.1 44.44,94.73 44.2,94.49 U1.8
UNNAMED_1_DIP28SOCKET_I172_VDDA: length 18.1
  BOTTOM w0.635: C17.1 57.54,111.26 U1.28
  BOTTOM w0.762: U1.27 U1.28 61.52,112.27 61.53,112.28 C30.2 62.74,115.57 H10.1
UNNAMED_1_DIP28SOCKET_I172_VI_1: length 14.5
  TOP w0.254: U1.1 43.31,116.64 43.3,116.65 R16.1 C8.1 C7.1
UNNAMED_1_DIP28SOCKET_I172_VI_2: length 25.1
  TOP w0.254: C13.1 C12.1 U1.6
  BOTTOM w0.254: R10.1 45.09,103.89 44.58,103.38 44.58,100.84 U1.6
UNNAMED_1_DIP28SOCKET_I172_VI_3: length 4.6
  TOP w0.254: H7.1 U1.10
UNNAMED_1_DIP28SOCKET_I172_VI_4: length 21.4
  TOP w0.254: C20.2 65.9,81.8 67.18,80.52 H21.1 ; C20.2 59.44,81.8 59.44,81.79 U1.16 U1.17 ; C20.2 H9.1
UNNAMED_1_DIP28SOCKET_I172_VIN1: length 16.1
  TOP w0.254: U1.2 42.42,109.73 42.17,109.48 C9.2 R13.2
  BOTTOM w0.254: R15.1 45.4,109.72 45.39,109.73 U1.2
UNNAMED_1_DIP28SOCKET_I172_VIN2: length 7.2
  BOTTOM w0.254: U1.7 44.2,97.03 44.44,96.78 R2.2 46.86,99.37 46.85,99.38 R4.1
UNNAMED_1_DIP28SOCKET_I172_VIN3: length 18
  TOP w0.254: R21.3 42.38,86.83 42.42,86.87 U1.11
  BOTTOM w0.254: U1.11 R31.1
UNNAMED_1_DIP28SOCKET_I172_VIN4: length 15.5
  TOP w0.254: U1.15 58.55,78.36 58.56,78.35 R20.2
  BOTTOM w0.254: U1.15 C14.2
UNNAMED_1_DIP28SOCKET_I172_VINC: length 4.3
  TOP w0.254: H9.2 U1.19
UNNAMED_1_DIP28SOCKET_I172_VOUT: length 21.5
  TOP w0.254: U1.3 42.42,107.19 42.17,107.43 C9.1 R13.1 24.77,107.43 H5.2
UNNAMED_1_DIP28SOCKET_I172_VREF: length 47.8
  TOP w0.254: R6.2 64.52,131.32 62.1,128.91 62.1,93.22 60.83,91.95 U1.20
  BOTTOM w0.254: C15.2 56.27,91.45 56.77,91.95 U1.20
UNNAMED_1_GRCAP_IC3RR_1: length 8.1
  TOP w0.254: H1.2 68.71,106.43 69.13,106.01 C3.1 69.13,100.7 68.95,100.52 C4.1
UNNAMED_1_GRCAP_IC3RR_2: length 21.7
  TOP w0.254: C4.2 C5.1 C6.1 ; C4.2 71,96.19 71.75,95.44 R25.1 ; C4.2 71,100.52 70.83,100.7 C3.2
UNNAMED_1_GRCAP_IC4HR_1: length 20.8
  TOP w0.254: R11.2 C12.2 C13.2 C10.1 C11.1
UNNAMED_1_GRCAP_IC4HR_2: length 12.2
  TOP w0.254: H5.1 18.29,109.47 17.4,108.59 17.4,104.59 17.39,104.59 C10.2 C11.2
UNNAMED_1_GRCAP_IC7RR_2: length 23.6
  TOP w0.254: v1(108.58,76.19) 108.58,78.73 108.59,78.74 C22.2 ; R34.1 R33.2 v1(101.46,76.19)
  BOTTOM w0.254: v1(101.46,76.19) v1(108.58,76.19)
UNNAMED_1_GRCAP_IC9HR_1: length 22.8
  TOP w0.254: C20.1 62.87,78.74 62.86,78.73 v1(62.86,76.19) ; R18.2 R20.1 v1(56.51,76.19)
  BOTTOM w0.254: v1(56.51,76.19) v1(62.86,76.19)
UNNAMED_1_GRHEADERSIP3_I131_1: length 12.7
  TOP w0.635: H8.2 H8.1 12.19,119.13 9.16,116.1 U5.3
UNNAMED_1_GRHEADERSIP3_I132_1: length 20
  TOP w0.635: U5.2 13.12,113.33 17.65,117.86 H18.1 H18.2
UNNAMED_1_GRHEADERSIP3_I132_3: length 5
  TOP w0.635: H18.3 21.45,126.37 21.46,126.37 R40.1
UNNAMED_1_GRLCD_I79_V0: length 23.1
  TOP w0.254: R35.2 18.16,59.82 7.49,49.15
UNNAMED_1_GRLCD_I79_VDDBL: length 22.5
  TOP w0.635: H31.1 13.97,73.91 11.68,71.63 11.68,60.96 U7.15
UNNAMED_1_GRLED_I155_CATHODE: length 4.8
  TOP w0.635: U8.2 R45.2
UNNAMED_1_GRLED_I169_CATHODE: length 4.8
  TOP w0.635: R46.2 U36.2
UNNAMED_1_GRLED_I170_CATHODE: length 4.8
  TOP w0.635: R48.2 U9.2
UNNAMED_1_GRLM317A_I135_ADJ: length 12.3
  TOP w0.635: R42.1 39.64,41.7 39.69,41.65 C25.1 44.63,41.65 44.64,41.66 U4.1 46.85,40.14 46.98,40 R41.1
UNNAMED_1_GRLM317A_I139_ADJ: length 18.6
  BOTTOM w0.762: R43.1 C28.1 R44.1 112.19,128.06 112.15,128.02 109.6,128.02 106.81,130.81 U39.1
UNNAMED_1_GRMBT2222_I163_BASE: length 4.5
  TOP w0.635: R49.2 54.76,14.99 54.7,15.05 U38.1
UNNAMED_1_GRMBT2222_I165_BASE: length 4.5
  TOP w0.635: R47.2 54.76,20.57 54.7,20.64 U37.1
UNNAMED_1_GRNELLCORDB9_I71_PDAN: length 21.7
  TOP w0.254: U5.5 5.48,122.96 12.7,130.18 18.16,130.18 H20.1
UNNAMED_1_GRNELLCORDB9_I71_PDCA: length 17
  TOP w0.254: H19.2 11.81,131.57 2.64,122.4 U5.9
UNNAMED_1_GRRES_I96_2: length 8
  TOP w0.762: H31.2 R36.2
UNNAMED_1_GRRES_I133_2: length 6.1
  TOP w0.635: R40.2 27.58,124.32 27.67,124.42 R39.1
UNNAMED_1_GRRES_IR4HR_2: length 6.1
  BOTTOM w0.254: R9.1 49.66,106.93 48.9,106.18 R10.2
UNNAMED_1_GRRES_IR4RR_2: length 6.4
  BOTTOM w0.254: R26.1 95.12,106.68 93.86,105.42 R27.2
UNNAMED_1_GRRES_IR6RR_2: length 6.3
  TOP w0.254: R25.2 R29.1
UNNAMED_1_GRRES_IR7HR_2: length 7.3
  TOP w0.254: R3.2 R11.1
UNNAMED_1_GRRES_IR12HR_1: length 11
  TOP w0.254: R18.1 40.77,73.15 38.73,75.18 H6.1
UNNAMED_1_GRRES_IRPBIASHR_1: length 6.2
  TOP w0.254: R37.1 53.28,133.87 53.33,133.82 R8.3
UNNAMED_1_GRRES_IRPBIASRR_2: length 6.4
  TOP w0.254: R38.2 R5.3
UNNAMED_1_HEADERSIP2_I40_1: length 23.3
  TOP w0.254: H4.1 77.13,79.5 R19.3 R19.2 U2.12
UNNAMED_1_HEADERSIP2_I40_2: length 9.8
  TOP w0.254: R34.2 85.98,73.66 83.69,75.95 H4.2
UNNAMED_1_HEADERSIP2_I56_2: length 25.3
  TOP w0.254: U1.12 R21.2 R21.1 31.15,79.5 H6.2
UNNAMED_1_HEADERSIP2_I66_2: length 10.3
  TOP w0.254: H12.2 R8.2
UNNAMED_1_POT_I4_2: length 7.6
  TOP w0.254: R5.2 R5.1 H13.2
UNNAMED_1_POT_I45_1: length 7.6
  TOP w0.254: R12.2 R12.1 H16.2
UNNAMED_1_POT_I46_1: length 7.6
  TOP w0.254: R7.2 R7.1 H14.2
VCM: length 208.8
  TOP w0.254: 48.9,116.32 47.62,117.6 R16.2 ; 48.9,116.32 v1(48.9,115.05) 48.9,104.65 ; 48.9,116.32 48.9,120.79 v1(51.18,123.06) ; v1(93.85,115.57) 93.85,125.6 88.14,131.32 R1.2 76.58,131.32 74.8,129.54 v1(74.8,123.06) ; v1(93.85,115.57) 93.85,114.87 93.86,114.86 93.86,104.65 ; v1(93.85,115.57) 91.82,117.6 R22.2 ; v1(47.12,81.53) 48.9,83.32 v1(48.9,89.16) v1(48.9,98.04) 48.9,104.65 ; 48.9,104.65 48.91,104.66 v1(53.73,104.66) ; v1(98.43,104.66) 93.87,104.66 93.86,104.65 ; v1(91.81,81.27) 93.85,83.31 93.85,83.82 93.86,83.83 v1(93.86,89.4) v1(93.86,97.8) 93.86,104.65
  BOTTOM w0.254: C16.2 59.44,104.66 59.44,104.65 U1.25 56.72,104.65 56.71,104.66 v1(53.73,104.66) ; C21.1 v1(91.81,81.27) ; C19.2 104.4,104.66 104.39,104.65 U2.25 101.42,104.65 101.41,104.66 v1(98.43,104.66) ; R28.2 v1(93.86,97.8) ; R31.2 v1(48.9,89.16) ; R9.2 49.66,114.3 v1(48.9,115.05) 47.62,115.05 46.36,113.79 R15.2 ; C14.1 47.11,80.2 47.12,80.21 v1(47.12,81.53) ; v1(51.18,123.06) v1(74.8,123.06) ; v1(48.9,98.04) R4.2 ; R23.2 91.31,113.03 v1(93.85,115.57) 95.12,114.3 R26.2 ; R32.2 v1(93.86,89.4)
VOUT_PD: length 95.4
  TOP w0.254: v1(48.13,122.17) C8.2 C7.2 45.35,127.7 45.34,127.71 45.34,131.57 41.02,135.89 v1(32.26,135.89) 32.26,134.44 32.27,134.43 R14.1 ; v1(89.15,124.84) 90.31,123.69 C1.1
  BOTTOM w0.254: H19.1 14.35,135.13 16,136.78 31.37,136.78 v1(32.26,135.89) ; v1(48.13,122.17) 50.8,124.84 v1(89.15,124.84)
VSUP: length 4.5
  TOP w0.762: H24.1 66.91,3.43 66.87,3.47 U3.4

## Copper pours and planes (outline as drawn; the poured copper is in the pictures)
GND on BOTTOM: 1.27,1.27 1.27,144.02 118.62,144.02 118.62,1.27

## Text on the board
Ref Des/Silkscreen Top: LCD | BL | Gain | 5V | UNO | Reg | Ibias | Vref | In5 | Out4 | Sup | Vcm | Reg_1.8V | PDA | IRC | In | IRA | In2 | Out1 | LED | Out2 | Out3 | Reg_5V | In3 | In4 | HR | RR | AHR | 9V | TESTN | TESTP | ARR
